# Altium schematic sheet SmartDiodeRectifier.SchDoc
size 431 x 279 mm; Date: Not shown in title block; ApprovedBy: Not shown in title block; CheckedBy: Not shown in title block; Author: Not shown in title block; CompanyName: Not shown in title block; Engineer: Not shown in title block; Organization: Not shown in title block; Address1: Not shown in title block; Address2: Not shown in title block; Address3: Not shown in title block; Address4: Not shown in title block; DocumentNumber: 1; Revision: Use project parameter SCH_Rev; SheetNumber: 2; SheetTotal: 3; PageSetup: Record=PageOptions¦CenterHorizontal=True¦CenterVertical=True¦PrintScale=0.96¦XCorrection=1.00¦YCorrection=1.00¦PrintKind=0¦BorderSize=5000000¦LeftOffset=0¦BottomOffset=0¦Orientation=2¦PaperLength=1000¦PaperWidth=1000¦Scale=100¦PaperSource=15¦PrintQuality=-3¦MediaType=1¦DitherType=10¦PrintScaleMode=1¦PaperKind=11x17¦PaperIndex=17
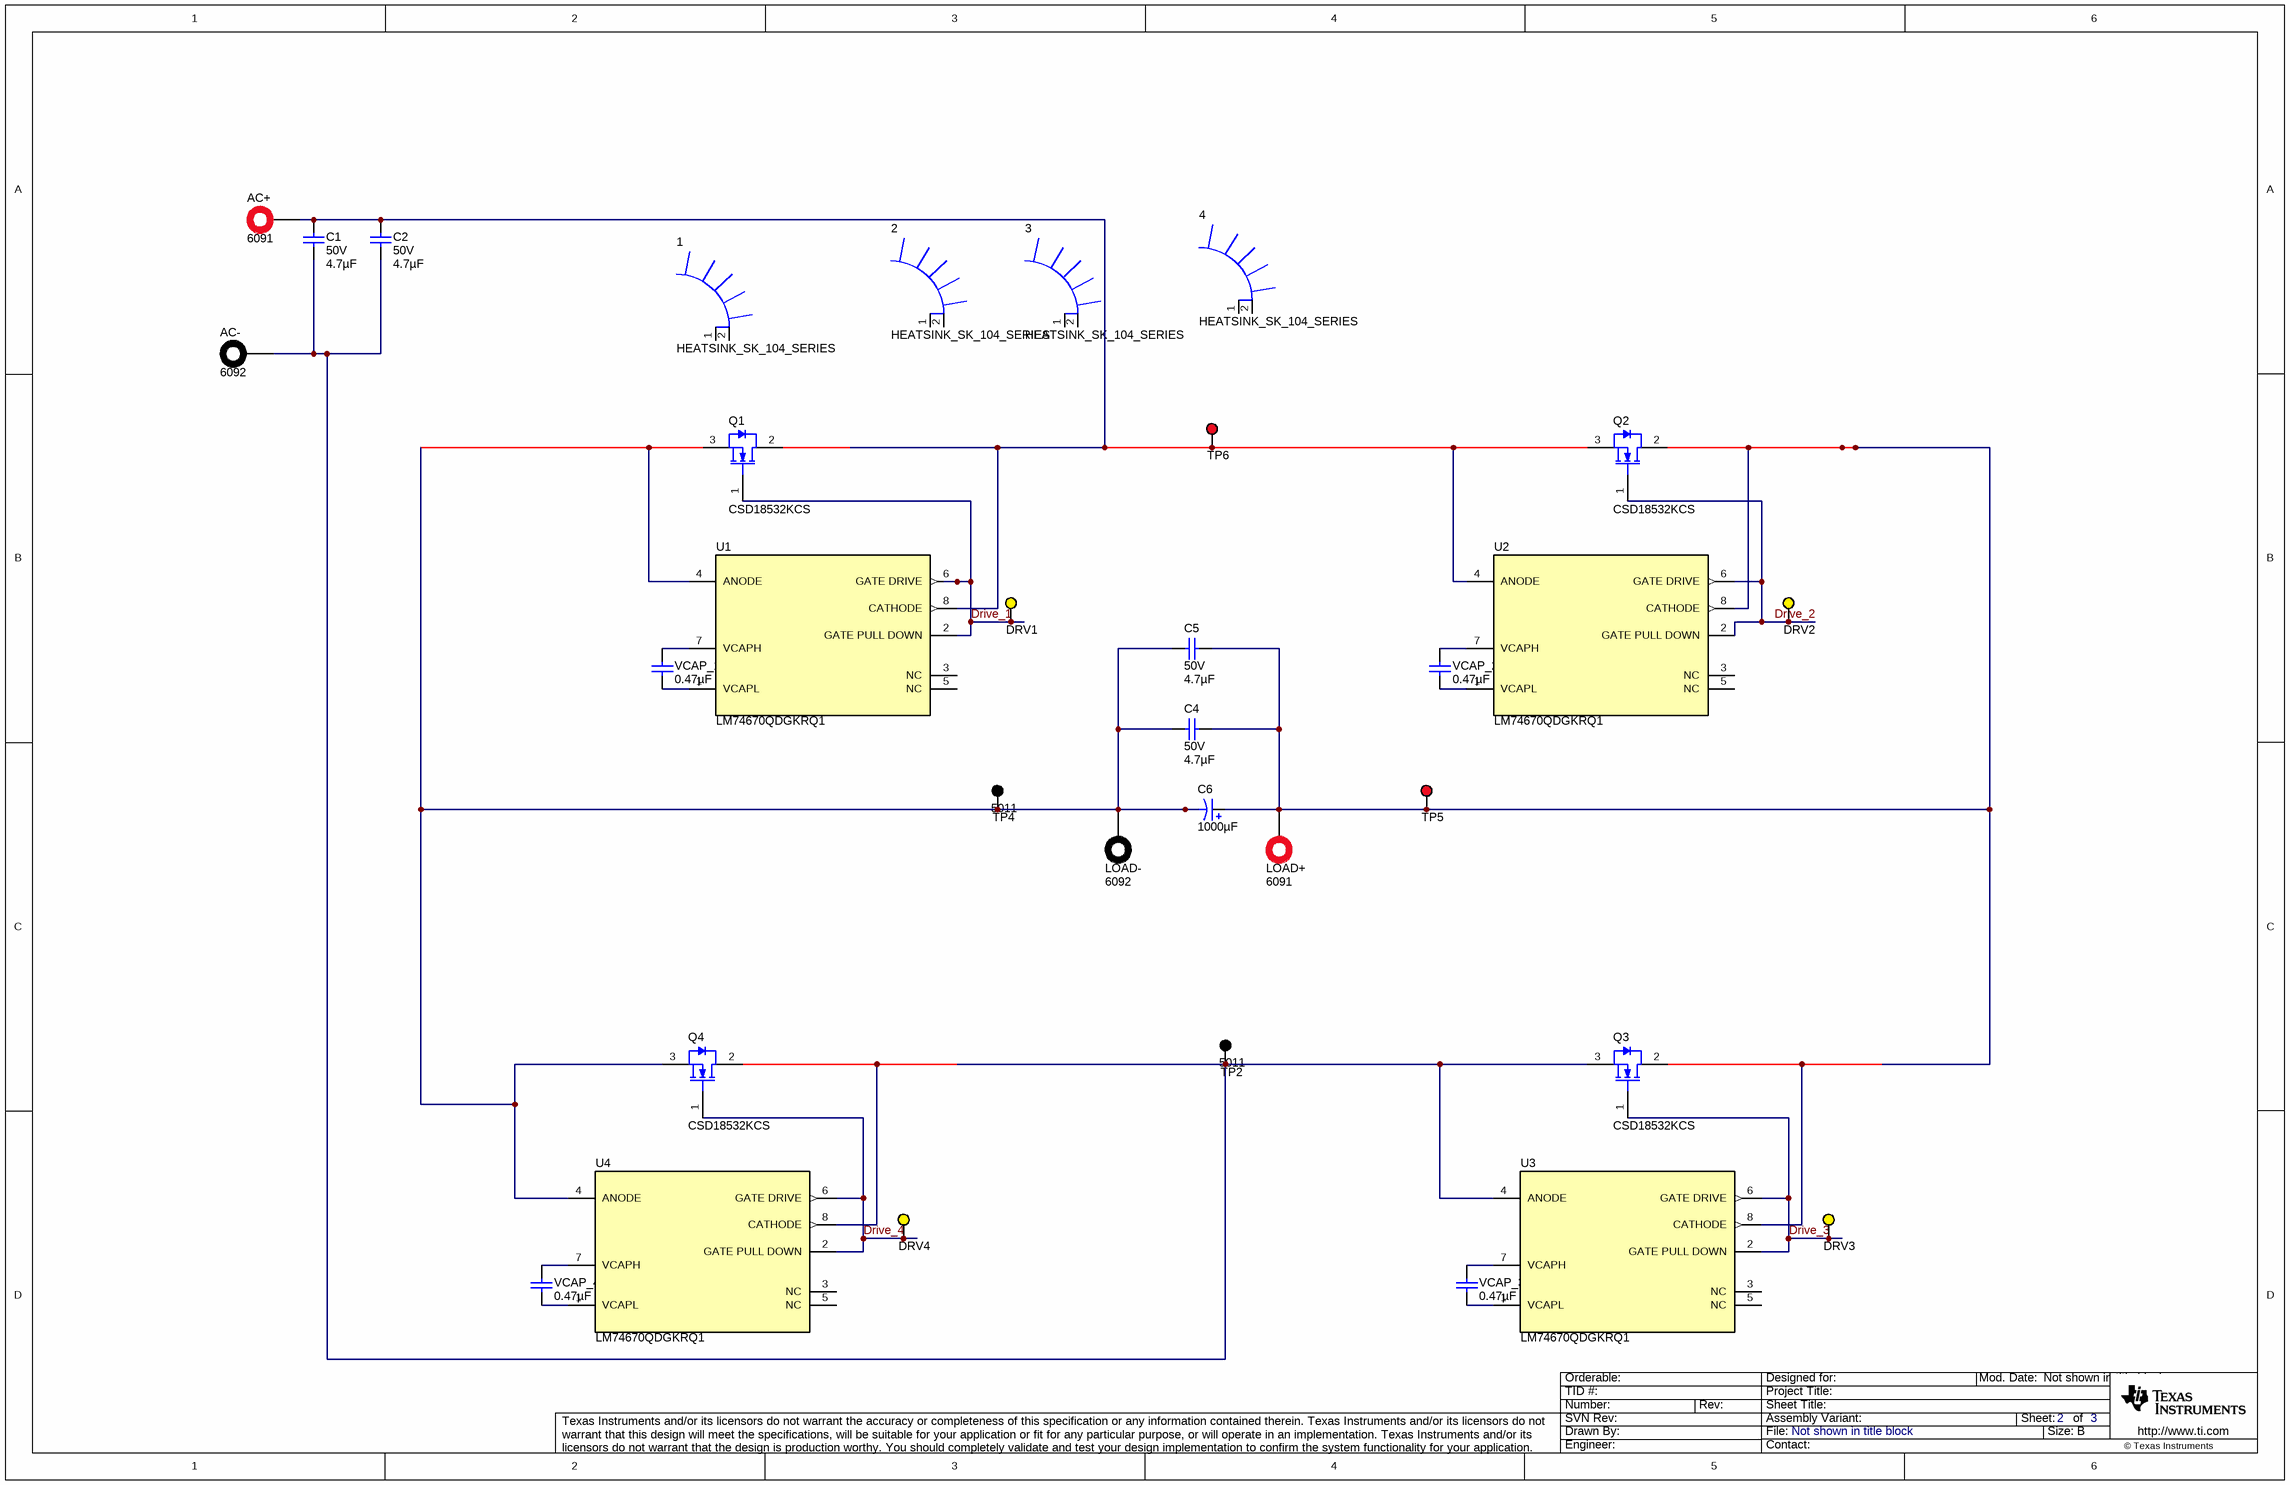
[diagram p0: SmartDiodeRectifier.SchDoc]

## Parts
1  HEATSINK_SK_104_SERIES  [HEATSINK_SK104_SERIES]
2  HEATSINK_SK_104_SERIES  [HEATSINK_SK104_SERIES]
3  HEATSINK_SK_104_SERIES  [HEATSINK_SK104_SERIES]
4  HEATSINK_SK_104_SERIES  [HEATSINK_SK104_SERIES]
AC+  6091  [6091]
AC-  6092  [6092]
C1  Value2: 50V  ValueDisplayed: 4.7µF  [1210]  (hidden comment: GRM32ER71H475KA88L)
C2  Value2: 50V  ValueDisplayed: 4.7µF  [1210]  (hidden comment: GRM32ER71H475KA88L)
C4  Value2: 50V  ValueDisplayed: 4.7µF  [1210]  (hidden comment: GRM32ER71H475KA88L)
C5  Value2: 50V  ValueDisplayed: 4.7µF  [1210]  (hidden comment: GRM32ER71H475KA88L)
C6  ValueDisplayed: 1000µF  [SM_RADIAL_J16]  (hidden comment: EEV-FK1H102M)
DRV1  5014  [Keystone5014]  (value not drawn)
DRV2  5014  [Keystone5014]  (value not drawn)
DRV3  5014  [Keystone5014]  (value not drawn)
DRV4  5014  [Keystone5014]  (value not drawn)
LOAD+  6091  [6091]
LOAD-  6092  [6092]
Q1  CSD18532KCS  [KCS0003A]
Q2  CSD18532KCS  [KCS0003A]
Q3  CSD18532KCS  [KCS0003A]
Q4  CSD18532KCS  [KCS0003A]
TP2  5011  [Keystone5011]
TP4  5011  [Keystone5011]
TP5  5010  [Keystone5010]  (value not drawn)
TP6  5010  [Keystone5010]  (value not drawn)
U1  LM74670QDGKRQ1  [DGK0008A_N]
U2  LM74670QDGKRQ1  [DGK0008A_N]
U3  LM74670QDGKRQ1  [DGK0008A_N]
U4  LM74670QDGKRQ1  [DGK0008A_N]
VCAP_1  ValueDisplayed: 0.47µF  [0805_HV]  (hidden comment: 08053D474KAT2A)
VCAP_2  ValueDisplayed: 0.47µF  [0805_HV]  (hidden comment: 08053D474KAT2A)
VCAP_3  ValueDisplayed: 0.47µF  [0805_HV]  (hidden comment: 08053D474KAT2A)
VCAP_4  ValueDisplayed: 0.47µF  [0805_HV]  (hidden comment: 08053D474KAT2A)

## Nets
Drive_1: DRV1.1 Q1.1(G) U1.2(GATE_PULL_DOWN) U1.6(GATE_DRIVE)
Drive_2: DRV2.1 Q2.1(G) U2.2(GATE_PULL_DOWN) U2.6(GATE_DRIVE)
Drive_3: DRV3.1 Q3.1(G) U3.2(GATE_PULL_DOWN) U3.6(GATE_DRIVE)
Drive_4: DRV4.1 Q4.1(G) U4.2(GATE_PULL_DOWN) U4.6(GATE_DRIVE)
NetAC+_1: AC+.1 C1.2 C2.2 Q1.2(D) Q2.3(S) TP6.1 U1.8(CATHODE) U2.4(ANODE)
NetAC-_1: AC-.1 C1.1 C2.1 Q3.3(S) Q4.2(D) TP2.1 U3.4(ANODE) U4.8(CATHODE)
NetC4_1: C4.1 C5.1 C6.2(-) LOAD-.1 Q1.3(S) Q4.3(S) TP4.1 U1.4(ANODE) U4.4(ANODE)
NetC4_2: C4.2 C5.2 C6.1(+) LOAD+.1 Q2.2(D) Q3.2(D) TP5.1 U2.8(CATHODE) U3.8(CATHODE)
NetU1_1: U1.1(VCAPL) VCAP_1.2
NetU1_7: U1.7(VCAPH) VCAP_1.1
NetU2_1: U2.1(VCAPL) VCAP_2.2
NetU2_7: U2.7(VCAPH) VCAP_2.1
NetU3_1: U3.1(VCAPL) VCAP_3.2
NetU3_7: U3.7(VCAPH) VCAP_3.1
NetU4_1: U4.1(VCAPL) VCAP_4.2
NetU4_7: U4.7(VCAPH) VCAP_4.1

Not connected (* = marked no-connect by the designer): 1 1 2; 2 1 2; 3 1 2; 4 1 2; U1 3(NC) 5(NC); U2 3(NC) 5(NC); U3 3(NC) 5(NC); U4 3(NC) 5(NC)

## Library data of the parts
1-4 = HEATSINK_SK_104_SERIES: Heatsink,  Vertical-mount TO-220; Manufacturer: Fisher elektronik; PartNumber: SK104-xx; area: 466.56 mm; Value: SK104-xx
AC+ LOAD+ = 6091: Standard Banana Jack, Insulated, Red; Manufacturer: Keystone; SymbolCreator: a0412235; CompType: Connector; U/M: EA
AC- LOAD- = 6092: Standard Banana Jack, Insulated, Black; Manufacturer: Keystone; SymbolCreator: a0412235; CompType: Connector; U/M: EA
C1 C2 C4 C5 = GRM32ER71H475KA88L: CAP, CERM, 4.7 µF, 50 V, +/- 10%, X7R, 1210; Manufacturer: MuRata; Polarized: N; CompType: Capacitor; Value: 4.7uF; U/M: EA; Cap_F: 0.0000047; Tolerance_%: 10; ESR_ohm: 0.002; Value1: 0.002 ohm; VDC_V: 50; TaMin_C: -55; TaMax_C: 125
C6 = EEV-FK1H102M: CAP, AL, 1000 µF, 50 V, +/- 20%, 0.073 ohm, SMD; Manufacturer: Panasonic; Polarized: Y; CompType: Capacitor; Value: 1000uF; U/M: EA; Cap_F: 0.001; Tolerance_%: 20; VDC_V: 50; Value2: 50V; ESR_ohm: 0.073; IRMS_A: 1.61; TaMin_C: -55; TaMax_C: 105; Cap_Case: J16
DRV1-DRV4 = 5014: Test Point, Multipurpose, Yellow, TH; Manufacturer: Keystone; CompType: Test Point Loop; U/M: EA
Q1-Q4 = CSD18532KCS: MOSFET, N-CH, 60 V, 100 A, KCS0003A; Manufacturer: Texas Instruments; Alternate Manufacturer: None; U/M: EA; ChType: N; Value: 60V; VdsMax_V: 60; Value1: 0.0053 ohm; Rdson45_ohm: 0.0053; Value2: 21 nC; QgTyp_nC: 21; Vgs_V: 20; IdsMax_A: 100
TP2 TP4 = 5011: Test Point, Multipurpose, Black, TH; Manufacturer: Keystone; CompType: Test Point Loop; U/M: EA
TP5 TP6 = 5010: Test Point, Multipurpose, Red, TH; Manufacturer: Keystone; CompType: Test Point Loop; U/M: EA
U1-U4 = LM74670QDGKRQ1: Reverse Polarity Protection Smart Diode Rectifier Controller, DGK0008A; Alternate PartNumber: LM74670QDGKTQ1; Manufacturer: Texas Instruments; SymbolCreator: Altium; CompType: IC; U/M: EA
VCAP_1-VCAP_4 = 08053D474KAT2A: CAP, CERM, 0.47 µF, 25 V, +/- 10%, X5R, 0805; Manufacturer: AVX; Polarized: N; CompType: Capacitor; Value: 0.47uF; U/M: EA; Cap_F: 0.00000047; Tolerance_%: 10; ESR_ohm: 0.017; Value1: 0.017 ohm; VDC_V: 25; Value2: 25V; TaMin_C: -55; TaMax_C: 85; Cap_Case: 0805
